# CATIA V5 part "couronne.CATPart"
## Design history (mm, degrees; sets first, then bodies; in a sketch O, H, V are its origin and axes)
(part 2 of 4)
    line L472 (-9.3364, -47.4236) -> (-9.2028, -47.1899)
    line L473 (-9.2028, -47.1899) -> (-9.0799, -46.966)
    line L474 (-9.0799, -46.966) -> (-8.9675, -46.7523)
    line L475 (-8.9675, -46.7523) -> (-8.8651, -46.5492)
    line L476 (-8.8651, -46.5492) -> (-8.804, -46.4225)
    arc A211 centre (0, 0) radius 47.25 from (-8.8041, -46.4225) to (-7.6045, -46.634) ccw
    line L477 (-7.6045, -46.634) -> (-7.6016, -46.666)
    line L478 (-7.6016, -46.666) -> (-7.5776, -46.8853)
    line L479 (-7.5776, -46.8853) -> (-7.548, -47.1179)
    line L480 (-7.548, -47.1179) -> (-7.5124, -47.3637)
    line L481 (-7.5124, -47.3637) -> (-7.4702, -47.6226)
    line L482 (-7.4702, -47.6226) -> (-7.421, -47.8944)
    line L483 (-7.421, -47.8944) -> (-7.3644, -48.1789)
    line L484 (-7.3644, -48.1789) -> (-7.2999, -48.476)
    line L485 (-7.2999, -48.476) -> (-7.2271, -48.7855)
    line L486 (-7.2271, -48.7855) -> (-7.1454, -49.1071)
    line L487 (-7.1454, -49.1071) -> (-7.0544, -49.4407)
    line L488 (-7.0544, -49.4407) -> (-7.0115, -49.5879)
    arc A212 centre (-6.5329, -49.4032) radius 0.513 from (-7.0115, -49.5879) to (-7.0052, -49.6036) ccw
    arc A213 centre (-6.5502, -49.3666) radius 0.513 from (-7.0052, -49.6036) to (-6.9552, -49.6814) ccw
    arc A214 centre (-6.5684, -49.3445) radius 0.513 from (-6.9552, -49.6814) to (-6.7664, -49.8178) ccw
    arc A215 centre (-6.5881, -49.3367) radius 0.513 from (-6.7664, -49.8178) to (-6.6686, -49.8434) ccw
    arc A216 centre (0, 0) radius 50.2875 from (-6.6686, -49.8434) to (-6.4517, -49.8719) ccw
    arc A217 centre (-6.4159, -49.3602) radius 0.513 from (-6.4517, -49.8719) to (-6.2238, -49.8358) ccw
    arc A218 centre (-6.438, -49.3697) radius 0.513 from (-6.2238, -49.8358) to (-6.0946, -49.7508) ccw
    arc A219 centre (-6.4627, -49.3935) radius 0.513 from (-6.0946, -49.7508) to (-6.0629, -49.7149) ccw
    arc A220 centre (-6.4904, -49.4314) radius 0.513 from (-6.0629, -49.7149) to (-6.0495, -49.6937) ccw
    line L489 (-6.0495, -49.6937) -> (-5.8935, -49.4314)
    line L490 (-5.8935, -49.4314) -> (-5.7254, -49.1373)
    line L491 (-5.7254, -49.1373) -> (-5.5691, -48.8524)
    line L492 (-5.5691, -48.8524) -> (-5.4243, -48.5772)
    line L493 (-5.4243, -48.5772) -> (-5.2906, -48.3119)
    line L494 (-5.2906, -48.3119) -> (-5.1676, -48.0569)
    line L495 (-5.1676, -48.0569) -> (-5.0549, -47.8124)
    line L496 (-5.0549, -47.8124) -> (-4.952, -47.5787)
    line L497 (-4.952, -47.5787) -> (-4.8587, -47.356)
    line L498 (-4.8587, -47.356) -> (-4.7744, -47.1447)
    line L499 (-4.7744, -47.1447) -> (-4.7245, -47.0132)
    arc A221 centre (0, 0) radius 47.25 from (-4.7245, -47.0132) to (-3.5112, -47.1194) ccw
    line L500 (-3.5112, -47.1194) -> (-3.5055, -47.151)
    line L501 (-3.5055, -47.151) -> (-3.4624, -47.3673)
    line L502 (-3.4624, -47.3673) -> (-3.4127, -47.5964)
    line L503 (-3.4127, -47.5964) -> (-3.3558, -47.8382)
    line L504 (-3.3558, -47.8382) -> (-3.2912, -48.0924)
    line L505 (-3.2912, -48.0924) -> (-3.2185, -48.3589)
    line L506 (-3.2185, -48.3589) -> (-3.1374, -48.6374)
    line L507 (-3.1374, -48.6374) -> (-3.0472, -48.9278)
    line L508 (-3.0472, -48.9278) -> (-2.9476, -49.2297)
    line L509 (-2.9476, -49.2297) -> (-2.8382, -49.543)
    line L510 (-2.8382, -49.543) -> (-2.7185, -49.8674)
    line L511 (-2.7185, -49.8674) -> (-2.663, -50.0103)
    arc A222 centre (-2.2023, -49.7846) radius 0.513 from (-2.663, -50.0103) to (-2.6553, -50.0254) ccw
    arc A223 centre (-2.2227, -49.7497) radius 0.513 from (-2.6553, -50.0254) to (-2.5988, -50.0986) ccw
    arc A224 centre (-2.2428, -49.7292) radius 0.513 from (-2.5988, -50.0986) to (-2.3987, -50.2179) ccw
    arc A225 centre (-2.2631, -49.7232) radius 0.513 from (-2.3987, -50.2179) to (-2.2991, -50.2349) ccw
    arc A226 centre (0, 0) radius 50.2875 from (-2.2991, -50.2349) to (-2.0805, -50.2444) ccw
    arc A227 centre (-2.0895, -49.7315) radius 0.513 from (-2.0805, -50.2444) to (-1.8566, -50.1886) ccw
    arc A228 centre (-2.1107, -49.743) radius 0.513 from (-1.8566, -50.1886) to (-1.7353, -50.0926) ccw
    arc A229 centre (-2.1332, -49.7688) radius 0.513 from (-1.7353, -50.0926) to (-1.7068, -50.0541) ccw
    arc A230 centre (-2.1575, -49.809) radius 0.513 from (-1.7068, -50.0541) to (-1.6954, -50.0318) ccw
    line L512 (-1.6954, -50.0318) -> (-1.5629, -49.757)
    line L513 (-1.5629, -49.757) -> (-1.421, -49.4493)
    line L514 (-1.421, -49.4493) -> (-1.2902, -49.1519)
    line L515 (-1.2902, -49.1519) -> (-1.1699, -48.8651)
    line L516 (-1.1699, -48.8651) -> (-1.0598, -48.5892)
    line L517 (-1.0598, -48.5892) -> (-0.9595, -48.3244)
    line L518 (-0.9595, -48.3244) -> (-0.8685, -48.071)
    line L519 (-0.8685, -48.071) -> (-0.7864, -47.8292)
    line L520 (-0.7864, -47.8292) -> (-0.7128, -47.5993)
    line L521 (-0.7128, -47.5993) -> (-0.6473, -47.3814)
    line L522 (-0.6473, -47.3814) -> (-0.6091, -47.2461)
    arc A231 centre (0, 0) radius 47.25 from (-0.6091, -47.2461) to (0.6089, -47.2461) ccw
    line L523 (0.6089, -47.2461) -> (0.6174, -47.2771)
    line L524 (0.6174, -47.2771) -> (0.6791, -47.4888)
    line L525 (0.6791, -47.4888) -> (0.7486, -47.7127)
    line L526 (0.7486, -47.7127) -> (0.8264, -47.9486)
    line L527 (0.8264, -47.9486) -> (0.9129, -48.1963)
    line L528 (0.9129, -48.1963) -> (1.0085, -48.4554)
    line L529 (1.0085, -48.4554) -> (1.1136, -48.7258)
    line L530 (1.1136, -48.7258) -> (1.2287, -49.0072)
    line L531 (1.2287, -49.0072) -> (1.3542, -49.2993)
    line L532 (1.3542, -49.2993) -> (1.4905, -49.6019)
    line L533 (1.4905, -49.6019) -> (1.638, -49.9146)
    line L534 (1.638, -49.9146) -> (1.7058, -50.0521)
    arc A232 centre (2.1451, -49.7871) radius 0.513 from (1.7058, -50.0521) to (1.7148, -50.0665) ccw
    arc A233 centre (2.1217, -49.7541) radius 0.513 from (1.7148, -50.0665) to (1.7775, -50.1344) ccw
    arc A234 centre (2.1, -49.7354) radius 0.513 from (1.7775, -50.1344) to (1.9872, -50.2359) ccw
    arc A235 centre (2.0792, -49.7312) radius 0.513 from (1.9872, -50.2359) to (2.0879, -50.2441) ccw
    arc A236 centre (0, 0) radius 50.2875 from (2.0879, -50.2441) to (2.3065, -50.2346) ccw
    arc A237 centre (2.2528, -49.7244) radius 0.513 from (2.3065, -50.2346) to (2.5247, -50.1595) ccw
    arc A238 centre (2.2327, -49.7376) radius 0.513 from (2.5247, -50.1595) to (2.6371, -50.0532) ccw
    arc A239 centre (2.2126, -49.7653) radius 0.513 from (2.6371, -50.0532) to (2.6622, -50.0124) ccw
    arc A240 centre (2.1919, -49.8075) radius 0.513 from (2.6622, -50.0124) to (2.6716, -49.9892) ccw
    line L535 (2.6716, -49.9892) -> (2.7797, -49.7039)
    line L536 (2.7797, -49.7039) -> (2.8942, -49.385)
    line L537 (2.8942, -49.385) -> (2.9986, -49.0773)
    line L538 (2.9986, -49.0773) -> (3.0934, -48.7811)
    line L539 (3.0934, -48.7811) -> (3.179, -48.4967)
    line L540 (3.179, -48.4967) -> (3.2559, -48.2241)
    line L541 (3.2559, -48.2241) -> (3.3245, -47.9638)
    line L542 (3.3245, -47.9638) -> (3.3851, -47.7157)
    line L543 (3.3851, -47.7157) -> (3.4384, -47.4803)
    line L544 (3.4384, -47.4803) -> (3.4848, -47.2575)
    line L545 (3.4848, -47.2575) -> (3.511, -47.1194)
    arc A241 centre (0, 0) radius 47.25 from (3.511, -47.1194) to (4.7243, -47.0132) ccw
    line L546 (4.7244, -47.0132) -> (4.7355, -47.0434)
    line L547 (4.7355, -47.0434) -> (4.8154, -47.2489)
    line L548 (4.8154, -47.2489) -> (4.9042, -47.4659)
    line L549 (4.9042, -47.4659) -> (5.0022, -47.6941)
    line L550 (5.0022, -47.6941) -> (5.11, -47.9333)
    line L551 (5.11, -47.9333) -> (5.2278, -48.1831)
    line L552 (5.2278, -48.1831) -> (5.3561, -48.4433)
    line L553 (5.3561, -48.4433) -> (5.4953, -48.7136)
    line L554 (5.4953, -48.7136) -> (5.6458, -48.9937)
    line L555 (5.6458, -48.9937) -> (5.808, -49.2832)
    line L556 (5.808, -49.2832) -> (5.9822, -49.5819)
    line L557 (5.9822, -49.5819) -> (6.0617, -49.713)
    arc A242 centre (6.4762, -49.4107) radius 0.513 from (6.0617, -49.713) to (6.0719, -49.7265) ccw
    arc A243 centre (6.45, -49.3798) radius 0.513 from (6.0719, -49.7265) to (6.1403, -49.7887) ccw
    arc A244 centre (6.4267, -49.3632) radius 0.513 from (6.1403, -49.7887) to (6.358, -49.8715) ccw
    arc A245 centre (6.4057, -49.3608) radius 0.513 from (6.358, -49.8715) to (6.459, -49.871) ccw
    arc A246 centre (0, 0) radius 50.2875 from (6.459, -49.871) to (6.6759, -49.8424) ccw
    arc A247 centre (6.578, -49.3388) radius 0.513 from (6.6759, -49.8424) to (6.8867, -49.7486) ccw
    arc A248 centre (6.5591, -49.3538) radius 0.513 from (6.8867, -49.7486) to (6.9895, -49.6329) ccw
    arc A249 centre (6.5415, -49.3831) radius 0.513 from (6.9895, -49.6329) to (7.0109, -49.59) ccw
    arc A250 centre (6.5245, -49.4269) radius 0.513 from (7.0109, -49.59) to (7.0183, -49.5661) ccw
    line L558 (7.0183, -49.5661) -> (7.1011, -49.2725)
    line L559 (7.1011, -49.2725) -> (7.1873, -48.9448)
    line L560 (7.1873, -48.9448) -> (7.2646, -48.6292)
    line L561 (7.2646, -48.6292) -> (7.3332, -48.3259)
    line L562 (7.3332, -48.3259) -> (7.3937, -48.0351)
    line L563 (7.3937, -48.0351) -> (7.4465, -47.7569)
    line L564 (7.4465, -47.7569) -> (7.4921, -47.4915)
    line L565 (7.4921, -47.4915) -> (7.531, -47.2391)
    line L566 (7.531, -47.2391) -> (7.5635, -46.9999)
    line L567 (7.5635, -46.9999) -> (7.5903, -46.774)
    line L568 (7.5903, -46.774) -> (7.6043, -46.6341)
    arc A251 centre (0, 0) radius 47.25 from (7.6043, -46.6341) to (8.8039, -46.4226) ccw
    line L569 (8.8039, -46.4226) -> (8.8176, -46.4516)
    line L570 (8.8176, -46.4516) -> (8.9151, -46.6494)
    line L571 (8.9151, -46.6494) -> (9.0225, -46.8579)
    line L572 (9.0225, -46.8579) -> (9.14, -47.0767)
    line L573 (9.14, -47.0767) -> (9.2682, -47.3055)
    line L574 (9.2682, -47.3055) -> (9.4073, -47.5441)
    line L575 (9.4073, -47.5441) -> (9.5578, -47.7922)
    line L576 (9.5578, -47.7922) -> (9.7201, -48.0493)
    line L577 (9.7201, -48.0493) -> (9.8944, -48.3152)
    line L578 (9.8944, -48.3152) -> (10.0812, -48.5895)
    line L579 (10.0812, -48.5895) -> (10.2807, -48.8719)
    line L580 (10.2807, -48.8719) -> (10.3714, -48.9955)
    arc A252 centre (10.7579, -48.6582) radius 0.513 from (10.3714, -48.9955) to (10.3827, -49.0081) ccw
    arc A253 centre (10.7292, -48.6298) radius 0.513 from (10.3827, -49.0081) to (10.4563, -49.0641) ccw
    arc A254 centre (10.7045, -48.6152) radius 0.513 from (10.4563, -49.0641) to (10.6804, -49.1276) ccw
    arc A255 centre (10.6834, -48.6146) radius 0.513 from (10.6804, -49.1276) to (10.781, -49.1183) ccw
    arc A256 centre (0, 0) radius 50.2875 from (10.7809, -49.1183) to (10.9946, -49.0709) ccw
    arc A257 centre (10.8532, -48.5778) radius 0.513 from (10.9946, -49.0709) to (11.1964, -48.959) ccw
    arc A258 centre (10.8356, -48.5943) radius 0.513 from (11.1964, -48.959) to (11.2887, -48.8349) ccw
    arc A259 centre (10.8206, -48.6251) radius 0.513 from (11.2887, -48.8349) to (11.3063, -48.7903) ccw
    arc A260 centre (10.8075, -48.6702) radius 0.513 from (11.3063, -48.7903) to (11.3115, -48.7658) ccw
    line L581 (11.3115, -48.7658) -> (11.3684, -48.4661)
    line L582 (11.3684, -48.4661) -> (11.4258, -48.1321)
    line L583 (11.4258, -48.1321) -> (11.4752, -47.811)
    line L584 (11.4752, -47.811) -> (11.5172, -47.5029)
    line L585 (11.5172, -47.5029) -> (11.5521, -47.2079)
    line L586 (11.5521, -47.2079) -> (11.5805, -46.9261)
    line L587 (11.5805, -46.9261) -> (11.6028, -46.6578)
    line L588 (11.6028, -46.6578) -> (11.6195, -46.403)
    line L589 (11.6195, -46.403) -> (11.631, -46.1619)
    line L590 (11.631, -46.1619) -> (11.638, -45.9345)
    line L591 (11.638, -45.9345) -> (11.6398, -45.7938)
    arc A261 centre (0, 0) radius 47.25 from (11.6399, -45.7938) to (12.8163, -45.4786) ccw
    line L592 (12.8163, -45.4786) -> (12.8325, -45.5064)
    line L593 (12.8325, -45.5064) -> (12.9469, -45.6949)
    line L594 (12.9469, -45.6949) -> (13.0721, -45.8932)
    line L595 (13.0721, -45.8932) -> (13.2083, -46.1009)
    line L596 (13.2083, -46.1009) -> (13.3559, -46.3177)
    line L597 (13.3559, -46.3177) -> (13.5153, -46.5433)
    line L598 (13.5153, -46.5433) -> (13.6868, -46.7773)
    line L599 (13.6868, -46.7773) -> (13.8709, -47.0193)
    line L600 (13.8709, -47.0193) -> (14.0677, -47.269)
    line L601 (14.0677, -47.269) -> (14.2777, -47.526)
    line L602 (14.2777, -47.526) -> (14.5011, -47.7899)
    line L603 (14.5011, -47.7899) -> (14.6021, -47.9051)
    arc A262 centre (14.9578, -47.5354) radius 0.513 from (14.6021, -47.9051) to (14.6146, -47.9167) ccw
    arc A263 centre (14.9268, -47.5096) radius 0.513 from (14.6146, -47.9167) to (14.6927, -47.9661) ccw
    arc A264 centre (14.9009, -47.4972) radius 0.513 from (14.6927, -47.9661) to (14.9215, -48.0098) ccw
    arc A265 centre (14.8798, -47.4985) radius 0.513 from (14.9215, -48.0098) to (15.0209, -47.9917) ccw
    arc A266 centre (0, 0) radius 50.2875 from (15.0209, -47.9917) to (15.2296, -47.9259) ccw
    arc A267 centre (15.0457, -47.447) radius 0.513 from (15.2296, -47.9259) to (15.4209, -47.7969) ccw
    arc A268 centre (15.0297, -47.465) radius 0.513 from (15.4209, -47.7969) to (15.502, -47.6652) ccw
    arc A269 centre (15.0174, -47.497) radius 0.513 from (15.502, -47.6652) to (15.5156, -47.6192) ccw
    arc A270 centre (15.0083, -47.543) radius 0.513 from (15.5156, -47.6192) to (15.5187, -47.5944) ccw
    line L604 (15.5187, -47.5944) -> (15.5493, -47.2908)
    line L605 (15.5493, -47.2908) -> (15.5773, -46.9532)
    line L606 (15.5773, -46.9532) -> (15.5986, -46.629)
    line L607 (15.5986, -46.629) -> (15.6135, -46.3183)
    line L608 (15.6135, -46.3183) -> (15.6226, -46.0214)
    line L609 (15.6226, -46.0214) -> (15.6263, -45.7383)
    line L610 (15.6263, -45.7383) -> (15.6251, -45.469)
    line L611 (15.6251, -45.469) -> (15.6195, -45.2137)
    line L612 (15.6195, -45.2137) -> (15.6101, -44.9725)
    line L613 (15.6101, -44.9725) -> (15.5972, -44.7453)
    line L614 (15.5972, -44.7453) -> (15.5867, -44.6051)
    arc A271 centre (0, 0) radius 47.25 from (15.5867, -44.6051) to (16.7313, -44.1885) ccw
    line L615 (16.7313, -44.1885) -> (16.7498, -44.2148)
    line L616 (16.7498, -44.2148) -> (16.8803, -44.3926)
    line L617 (16.8803, -44.3926) -> (17.0222, -44.5793)
    line L618 (17.0222, -44.5793) -> (17.176, -44.7743)
    line L619 (17.176, -44.7743) -> (17.3419, -44.9775)
    line L620 (17.3419, -44.9775) -> (17.5204, -45.1883)
    line L621 (17.5204, -45.1883) -> (17.7117, -45.4064)
    line L622 (17.7117, -45.4064) -> (17.9161, -45.6314)
    line L623 (17.9161, -45.6314) -> (18.1339, -45.863)
    line L624 (18.1339, -45.863) -> (18.3655, -46.1007)
    line L625 (18.3655, -46.1007) -> (18.6111, -46.3442)
    line L626 (18.6111, -46.3442) -> (18.7218, -46.4502)
    arc A272 centre (19.0439, -46.0509) radius 0.513 from (18.7218, -46.4502) to (18.7352, -46.4606) ccw
    arc A273 centre (19.0107, -46.0279) radius 0.513 from (18.7352, -46.4606) to (18.8173, -46.503) ccw
    arc A274 centre (18.9838, -46.0178) radius 0.513 from (18.8173, -46.503) to (19.049, -46.5266) ccw
    arc A275 centre (18.9629, -46.0209) radius 0.513 from (19.049, -46.5266) to (19.1465, -46.4999) ccw
    arc A276 centre (0, 0) radius 50.2875 from (19.1465, -46.5) to (19.3486, -46.4162) ccw
    arc A277 centre (19.1237, -45.9551) radius 0.513 from (19.3486, -46.4162) to (19.5279, -46.271) ccw
    arc A278 centre (19.1093, -45.9744) radius 0.513 from (19.5279, -46.271) to (19.5973, -46.1327) ccw
    arc A279 centre (19.0999, -46.0074) radius 0.513 from (19.5973, -46.1327) to (19.6068, -46.0858) ccw
    arc A280 centre (19.0948, -46.054) radius 0.513 from (19.6068, -46.0858) to (19.6078, -46.0608) ccw
    line L627 (19.6078, -46.0608) -> (19.6118, -45.7556)
    line L628 (19.6118, -45.7556) -> (19.6103, -45.4168)
    line L629 (19.6103, -45.4168) -> (19.6032, -45.092)
    line L630 (19.6032, -45.092) -> (19.591, -44.7813)
    line L631 (19.591, -44.7813) -> (19.5742, -44.4847)
    line L632 (19.5742, -44.4847) -> (19.5532, -44.2023)
    line L633 (19.5532, -44.2023) -> (19.5285, -43.9342)
    line L634 (19.5285, -43.9342) -> (19.5007, -43.6803)
    line L635 (19.5007, -43.6803) -> (19.4703, -43.4409)
    line L636 (19.4703, -43.4409) -> (19.4376, -43.2157)
    line L637 (19.4376, -43.2157) -> (19.415, -43.0769)
    arc A281 centre (0, 0) radius 47.25 from (19.415, -43.0769) to (20.5189, -42.5622) ccw
    line L638 (20.5189, -42.5622) -> (20.5397, -42.5867)
    line L639 (20.5397, -42.5867) -> (20.6851, -42.7525)
    line L640 (20.6851, -42.7525) -> (20.8427, -42.9261)
    line L641 (20.8427, -42.9261) -> (21.0129, -43.107)
    line L642 (21.0129, -43.107) -> (21.196, -43.2949)
    line L643 (21.196, -43.2949) -> (21.3921, -43.4893)
    line L644 (21.3921, -43.4893) -> (21.6017, -43.6899)
    line L645 (21.6017, -43.6899) -> (21.8249, -43.8963)
    line L646 (21.8249, -43.8963) -> (22.0622, -44.108)
    line L647 (22.0622, -44.108) -> (22.3136, -44.3246)
    line L648 (22.3136, -44.3246) -> (22.5794, -44.5457)
    line L649 (22.5794, -44.5457) -> (22.6989, -44.6417)
    arc A282 centre (22.985, -44.2159) radius 0.513 from (22.6989, -44.6417) to (22.7132, -44.6509) ccw
    arc A283 centre (22.9499, -44.1958) radius 0.513 from (22.7132, -44.6509) to (22.7987, -44.686) ccw
    arc A284 centre (22.9223, -44.1881) radius 0.513 from (22.7987, -44.686) to (23.0316, -44.6894) ccw
    arc A285 centre (22.9017, -44.1931) radius 0.513 from (23.0316, -44.6894) to (23.1264, -44.6543) ccw
    arc A286 centre (0, 0) radius 50.2875 from (23.1264, -44.6543) to (23.3204, -44.5532) ccw
    arc A287 centre (23.0562, -44.1135) radius 0.513 from (23.3204, -44.5532) to (23.4864, -44.3929) ccw
    arc A288 centre (23.0436, -44.134) radius 0.513 from (23.4864, -44.3929) to (23.5435, -44.2491) ccw
    arc A289 centre (23.037, -44.1676) radius 0.513 from (23.5435, -44.2491) to (23.5489, -44.2015) ccw
    arc A290 centre (23.036, -44.2146) radius 0.513 from (23.5489, -44.2015) to (23.5476, -44.1766) ccw
    line L650 (23.5476, -44.1766) -> (23.525, -43.8723)
    line L651 (23.525, -43.8723) -> (23.494, -43.5349)
    line L652 (23.494, -43.5349) -> (23.4586, -43.2119)
    line L653 (23.4586, -43.2119) -> (23.4194, -42.9034)
    line L654 (23.4194, -42.9034) -> (23.3768, -42.6094)
    line L655 (23.3768, -42.6094) -> (23.3313, -42.3299)
    line L656 (23.3313, -42.3299) -> (23.2833, -42.065)
    line L657 (23.2833, -42.065) -> (23.2335, -41.8145)
    line L658 (23.2335, -41.8145) -> (23.1823, -41.5786)
    line L659 (23.1823, -41.5786) -> (23.1302, -41.3571)
    line L660 (23.1302, -41.3571) -> (23.0955, -41.2209)
    arc A291 centre (0, 0) radius 47.25 from (23.0955, -41.2209) to (24.1504, -40.6118) ccw
    line L661 (24.1504, -40.6118) -> (24.1732, -40.6345)
    line L662 (24.1732, -40.6345) -> (24.3325, -40.787)
    line L663 (24.3325, -40.787) -> (24.5047, -40.9461)
    line L664 (24.5047, -40.9461) -> (24.69, -41.1115)
    line L665 (24.69, -41.1115) -> (24.8887, -41.2828)
    line L666 (24.8887, -41.2828) -> (25.1011, -41.4594)
    line L667 (25.1011, -41.4594) -> (25.3273, -41.641)
    line L668 (25.3273, -41.641) -> (25.5677, -41.8271)
    line L669 (25.5677, -41.8271) -> (25.8225, -42.0173)
    line L670 (25.8225, -42.0173) -> (26.0918, -42.2112)
    line L671 (26.0918, -42.2112) -> (26.3759, -42.4083)
    line L672 (26.3759, -42.4083) -> (26.5033, -42.4935)
    arc A292 centre (26.7512, -42.0443) radius 0.513 from (26.5033, -42.4935) to (26.5183, -42.5014) ccw
    arc A293 centre (26.7145, -42.0274) radius 0.513 from (26.5183, -42.5014) to (26.6066, -42.5289) ccw
    arc A294 centre (26.6863, -42.0222) radius 0.513 from (26.6066, -42.5289) to (26.8389, -42.512) ccw
    arc A295 centre (26.6663, -42.0289) radius 0.513 from (26.8389, -42.512) to (26.9302, -42.4688) ccw
    arc A296 centre (0, 0) radius 50.2875 from (26.9302, -42.4688) to (27.1147, -42.3512) ccw
    arc A297 centre (26.8132, -41.9362) radius 0.513 from (27.1148, -42.3512) to (27.2661, -42.177) ccw
    arc A298 centre (26.8024, -41.9577) radius 0.513 from (27.2661, -42.177) to (27.3105, -42.0288) ccw
    arc A299 centre (26.7988, -41.9918) radius 0.513 from (27.3105, -42.0288) to (27.3117, -41.9809) ccw
    arc A300 centre (26.8019, -42.0386) radius 0.513 from (27.3117, -41.9809) to (27.3083, -41.9561) ccw
    line L673 (27.3083, -41.9561) -> (27.2592, -41.655)
    line L674 (27.2592, -41.655) -> (27.1989, -41.3216)
    line L675 (27.1989, -41.3216) -> (27.1355, -41.0029)
    line L676 (27.1355, -41.0029) -> (27.0696, -40.699)
    line L677 (27.0696, -40.699) -> (27.0015, -40.4098)
    line L678 (27.0015, -40.4098) -> (26.9318, -40.1354)
    line L679 (26.9318, -40.1354) -> (26.8609, -39.8756)
    line L680 (26.8609, -39.8756) -> (26.7895, -39.6305)
    line L681 (26.7895, -39.6305) -> (26.7179, -39.3999)
    line L682 (26.7179, -39.3999) -> (26.6466, -39.1838)
    line L683 (26.6466, -39.1838) -> (26.6003, -39.0511)
    arc A301 centre (0, 0) radius 47.25 from (26.6003, -39.0511) to (27.598, -38.3525) ccw
    line L684 (27.598, -38.3525) -> (27.6227, -38.373)
    line L685 (27.6227, -38.373) -> (27.7947, -38.5111)
    line L686 (27.7947, -38.5111) -> (27.9801, -38.6546)
    line L687 (27.9801, -38.6546) -> (28.1791, -38.8032)
    line L688 (28.1791, -38.8032) -> (28.392, -38.9565)
    line L689 (28.392, -38.9565) -> (28.619, -39.1139)
    line L690 (28.619, -39.1139) -> (28.8602, -39.2751)
    line L691 (28.8602, -39.2751) -> (29.1159, -39.4396)
    line L692 (29.1159, -39.4396) -> (29.3863, -39.6069)
    line L693 (29.3863, -39.6069) -> (29.6715, -39.7765)
    line L694 (29.6715, -39.7765) -> (29.9716, -39.9481)
    line L695 (29.9716, -39.9481) -> (30.106, -40.0218)
    arc A302 centre (30.3138, -39.5528) radius 0.513 from (30.106, -40.0218) to (30.1217, -40.0285) ccw
    arc A303 centre (30.2758, -39.5392) radius 0.513 from (30.1217, -40.0285) to (30.212, -40.0482) ccw
    arc A304 centre (30.2473, -39.5364) radius 0.513 from (30.212, -40.0482) to (30.4419, -40.011) ccw
    arc A305 centre (30.2278, -39.5448) radius 0.513 from (30.4419, -40.011) to (30.5291, -39.96) ccw
    arc A306 centre (0, 0) radius 50.2875 from (30.5292, -39.96) to (30.7027, -39.8268) ccw
    arc A307 centre (30.3662, -39.4397) radius 0.513 from (30.7027, -39.8268) to (30.8384, -39.6401) ccw
    arc A308 centre (30.3573, -39.462) radius 0.513 from (30.8384, -39.6401) to (30.8696, -39.4886) ccw
    arc A309 centre (30.3566, -39.4963) radius 0.513 from (30.8696, -39.4886) to (30.8666, -39.4408) ccw
    arc A310 centre (30.3638, -39.5427) radius 0.513 from (30.8666, -39.4408) to (30.8611, -39.4164) ccw
    line L696 (30.8611, -39.4164) -> (30.786, -39.1207)
    line L697 (30.786, -39.1207) -> (30.6968, -38.7938)
    line L698 (30.6968, -38.7938) -> (30.6059, -38.4819)
    line L699 (30.6059, -38.4819) -> (30.5137, -38.1849)
    line L700 (30.5137, -38.1849) -> (30.4207, -37.9027)
    line L701 (30.4207, -37.9027) -> (30.3273, -37.6354)
    line L702 (30.3273, -37.6354) -> (30.2341, -37.3828)
    line L703 (30.2341, -37.3828) -> (30.1416, -37.1448)
    line L704 (30.1416, -37.1448) -> (30.0502, -36.9214)
    line L705 (30.0502, -36.9214) -> (29.9603, -36.7123)
    line L706 (29.9603, -36.7123) -> (29.9026, -36.5841)
    arc A311 centre (0, 0) radius 47.25 from (29.9026, -36.5841) to (30.8357, -35.8012) ccw
    line L707 (30.8356, -35.8012) -> (30.862, -35.8195)
    line L708 (30.862, -35.8195) -> (31.0454, -35.942)
    line L709 (31.0454, -35.942) -> (31.2426, -36.0689)
    line L710 (31.2426, -36.0689) -> (31.4538, -36.1996)
    line L711 (31.4538, -36.1996) -> (31.6793, -36.3337)
    line L712 (31.6793, -36.3337) -> (31.9191, -36.4708)
    line L713 (31.9191, -36.4708) -> (32.1734, -36.6103)
    line L714 (32.1734, -36.6103) -> (32.4425, -36.7519)
    line L715 (32.4425, -36.7519) -> (32.7264, -36.895)
    line L716 (32.7264, -36.895) -> (33.0253, -37.0391)
    line L717 (33.0253, -37.0391) -> (33.3393, -37.1839)
    line L718 (33.3393, -37.1839) -> (33.4796, -37.2456)
    arc A312 centre (33.6457, -36.7603) radius 0.513 from (33.4796, -37.2456) to (33.4958, -37.2509) ccw
    arc A313 centre (33.6067, -36.75) radius 0.513 from (33.4958, -37.2509) to (33.5874, -37.2626) ccw
    arc A314 centre (33.578, -36.7497) radius 0.513 from (33.5874, -37.2626) to (33.8133, -37.2056) ccw
    arc A315 centre (33.5594, -36.7598) radius 0.513 from (33.8133, -37.2056) to (33.8957, -37.1472) ccw
    arc A316 centre (0, 0) radius 50.2875 from (33.8957, -37.1472) to (34.057, -36.9994) ccw
    arc A317 centre (33.688, -36.643) radius 0.513 from (34.057, -36.9993) to (34.1759, -36.8016) ccw
    arc A318 centre (33.6811, -36.6661) radius 0.513 from (34.1759, -36.8016) to (34.1938, -36.6479) ccw
    arc A319 centre (33.6835, -36.7002) radius 0.513 from (34.1938, -36.6479) to (34.1867, -36.6005) ccw
    arc A320 centre (33.6947, -36.7458) radius 0.513 from (34.1867, -36.6005) to (34.179, -36.5767) ccw
    line L719 (34.179, -36.5767) -> (34.0784, -36.2886)
    line L720 (34.0784, -36.2886) -> (33.9611, -35.9708)
    line L721 (33.9611, -35.9708) -> (33.8434, -35.6679)
    line L722 (33.8434, -35.6679) -> (33.7256, -35.3801)
    line L723 (33.7256, -35.3801) -> (33.6083, -35.1072)
    line L724 (33.6083, -35.1072) -> (33.492, -34.849)
    line L725 (33.492, -34.849) -> (33.3772, -34.6055)
    line L726 (33.3772, -34.6055) -> (33.2643, -34.3765)
    line L727 (33.2643, -34.3765) -> (33.1537, -34.1618)
    line L728 (33.1537, -34.1618) -> (33.046, -33.9614)
    line L729 (33.046, -33.9614) -> (32.9773, -33.8387)
    arc A321 centre (0, 0) radius 47.25 from (32.9773, -33.8387) to (33.8386, -32.9775) ccw
    line L730 (33.8386, -32.9775) -> (33.8665, -32.9934)
    line L731 (33.8665, -32.9934) -> (34.0598, -33.0995)
    line L732 (34.0598, -33.0995) -> (34.2674, -33.2087)
    line L733 (34.2674, -33.2087) -> (34.4892, -33.3205)
    line L734 (34.4892, -33.3205) -> (34.7254, -33.4344)
    line L735 (34.7254, -33.4344) -> (34.9762, -33.55)
    line L736 (34.9762, -33.55) -> (35.2418, -33.6669)
    line L737 (35.2418, -33.6669) -> (35.5222, -33.7845)
    line L738 (35.5222, -33.7845) -> (35.8175, -33.9023)
    line L739 (35.8175, -33.9023) -> (36.1278, -34.0199)
    line L740 (36.1278, -34.0199) -> (36.4532, -34.1367)
    line L741 (36.4532, -34.1367) -> (36.5984, -34.186)
    arc A322 centre (36.7216, -33.688) radius 0.513 from (36.5984, -34.186) to (36.6149, -34.1898) ccw
    arc A323 centre (36.6817, -33.6811) radius 0.513 from (36.6149, -34.1898) to (36.7073, -34.1935) ccw
    arc A324 centre (36.6532, -33.6834) radius 0.513 from (36.7073, -34.1935) to (36.9273, -34.117) ccw
    arc A325 centre (36.6355, -33.695) radius 0.513 from (36.9273, -34.117) to (37.0043, -34.0516) ccw
    arc A326 centre (0, 0) radius 50.2875 from (37.0043, -34.0516) to (37.1521, -33.8903) ccw
    arc A327 centre (36.7535, -33.5675) radius 0.513 from (37.1521, -33.8903) to (37.2533, -33.6829) ccw
    arc A328 centre (36.7486, -33.591) radius 0.513 from (37.2533, -33.6829) to (37.2577, -33.5283) ccw
    arc A329 centre (36.7539, -33.6249) radius 0.513 from (37.2577, -33.5283) to (37.2465, -33.4817) ccw
    arc A330 centre (36.7691, -33.6693) radius 0.513 from (37.2465, -33.4817) to (37.2368, -33.4586) ccw
    line L742 (37.2368, -33.4586) -> (37.1115, -33.1804)
    line L743 (37.1115, -33.1804) -> (36.967, -32.874)
    line L744 (36.967, -32.874) -> (36.8233, -32.5826)
    line L745 (36.8233, -32.5826) -> (36.6809, -32.3061)
    line L746 (36.6809, -32.3061) -> (36.5402, -32.0444)
    line L747 (36.5402, -32.0444) -> (36.4019, -31.7974)
    line L748 (36.4019, -31.7974) -> (36.2662, -31.5648)
    line L749 (36.2662, -31.5648) -> (36.1338, -31.3465)
    line L750 (36.1338, -31.3465) -> (36.005, -31.1423)
    line L751 (36.005, -31.1423) -> (35.8802, -30.952)
    line L752 (35.8802, -30.952) -> (35.8011, -30.8358)
    arc A331 centre (0, 0) radius 47.25 from (35.8011, -30.8358) to (36.584, -29.9027) ccw
    line L753 (36.584, -29.9027) -> (36.6132, -29.9162)
    line L754 (36.6132, -29.9162) -> (36.815, -30.005)
    line L755 (36.815, -30.005) -> (37.0313, -30.0957)
    line L756 (37.0313, -30.0957) -> (37.262, -30.1877)
    line L757 (37.262, -30.1877) -> (37.5073, -30.2807)
    line L758 (37.5073, -30.2807) -> (37.7672, -30.374)
    line L759 (37.7672, -30.374) -> (38.0419, -30.4673)
    line L760 (38.0419, -30.4673) -> (38.3315, -30.5599)
    line L761 (38.3315, -30.5599) -> (38.636, -30.6516)
    line L762 (38.636, -30.6516) -> (38.9553, -30.7417)
    line L763 (38.9553, -30.7417) -> (39.2897, -30.8297)
    line L764 (39.2897, -30.8297) -> (39.4386, -30.8661)
    arc A332 centre (39.518, -30.3593) radius 0.513 from (39.4386, -30.8661) to (39.4554, -30.8685) ccw
    arc A333 centre (39.4777, -30.3559) radius 0.513 from (39.4554, -30.8685) to (39.5478, -30.8641) ccw
    arc A334 centre (39.4494, -30.3607) radius 0.513 from (39.5478, -30.8641) to (39.7603, -30.7687) ccw
    arc A335 centre (39.4328, -30.3738) radius 0.513 from (39.7603, -30.7687) to (39.8313, -30.6969) ccw
    arc A336 centre (0, 0) radius 50.2875 from (39.8313, -30.6969) to (39.9645, -30.5233) ccw
    arc A337 centre (39.5392, -30.2364) radius 0.513 from (39.9645, -30.5233) to (40.0472, -30.3079) ccw
    arc A338 centre (39.5364, -30.2604) radius 0.513 from (40.0472, -30.3079) to (40.0381, -30.1534) ccw
    arc A339 centre (39.5447, -30.2936) radius 0.513 from (40.0381, -30.1534) to (40.0229, -30.108) ccw
    arc A340 centre (39.5636, -30.3366) radius 0.513 from (40.0229, -30.108) to (40.0112, -30.0859) ccw
    line L765 (40.0112, -30.0859) -> (39.8621, -29.8197)
    line L766 (39.8621, -29.8197) -> (39.6914, -29.527)
    line L767 (39.6914, -29.527) -> (39.5229, -29.2492)
    line L768 (39.5229, -29.2492) -> (39.3569, -28.9862)
    line L769 (39.3569, -28.9862) -> (39.1941, -28.7378)
    line L770 (39.1941, -28.7378) -> (39.0347, -28.5037)
    line L771 (39.0347, -28.5037) -> (38.8793, -28.2838)
    line L772 (38.8793, -28.2838) -> (38.7283, -28.0779)
    line L773 (38.7283, -28.0779) -> (38.5822, -27.8857)
    line L774 (38.5822, -27.8857) -> (38.4413, -27.7071)
    line L775 (38.4413, -27.7071) -> (38.3524, -27.5982)
    arc A341 centre (0, 0) radius 47.25 from (38.3523, -27.5982) to (39.051, -26.6005) ccw
    line L776 (39.051, -26.6004) -> (39.0812, -26.6113)
    line L777 (39.0812, -26.6113) -> (39.2901, -26.6822)
    line L778 (39.2901, -26.6822) -> (39.5134, -26.7537)
    line L779 (39.5134, -26.7537) -> (39.7512, -26.8253)
    line L780 (39.7512, -26.8253) -> (40.0037, -26.8965)
    line L781 (40.0037, -26.8965) -> (40.2708, -26.9668)
    line L782 (40.2708, -26.9668) -> (40.5526, -27.0357)
    line L783 (40.5526, -27.0357) -> (40.8491, -27.1028)
    line L784 (40.8491, -27.1028) -> (41.1604, -27.1676)
    line L785 (41.1604, -27.1676) -> (41.4864, -27.2295)
    line L786 (41.4864, -27.2295) -> (41.8272, -27.288)
    line L787 (41.8272, -27.288) -> (41.9787, -27.3114)
    arc A342 centre (42.0136, -26.7995) radius 0.513 from (41.9787, -27.3114) to (41.9957, -27.3122) ccw
    arc A343 centre (41.9731, -26.7997) radius 0.513 from (41.9957, -27.3122) to (42.0873, -27.2999) ccw
    arc A344 centre (41.9454, -26.8069) radius 0.513 from (42.0873, -27.2999) to (42.2906, -27.1863) ccw
    arc A345 centre (41.93, -26.8215) radius 0.513 from (42.2906, -27.1863) to (42.3551, -27.1086) ccw
    arc A346 centre (0, 0) radius 50.2875 from (42.3552, -27.1085) to (42.4727, -26.924) ccw
    arc A347 centre (42.024, -26.6753) radius 0.513 from (42.4727, -26.924) to (42.5363, -26.7022) ccw
    arc A348 centre (42.0233, -26.6994) radius 0.513 from (42.5363, -26.7022) to (42.5138, -26.5491) ccw
    arc A349 centre (42.0344, -26.7318) radius 0.513 from (42.5138, -26.5491) to (42.4947, -26.5052) ccw
    arc A350 centre (42.0571, -26.7729) radius 0.513 from (42.4947, -26.5052) to (42.4811, -26.4842) ccw
    line L788 (42.4811, -26.4842) -> (42.3094, -26.232)
    line L789 (42.3094, -26.232) -> (42.1138, -25.9553)
    line L790 (42.1138, -25.9553) -> (41.9217, -25.6933)
    line L791 (41.9217, -25.6933) -> (41.7335, -25.4457)
    line L792 (41.7335, -25.4457) -> (41.5496, -25.2124)
    line L793 (41.5496, -25.2124) -> (41.3704, -24.9932)
    line L794 (41.3704, -24.9932) -> (41.1964, -24.7877)
    line L795 (41.1964, -24.7877) -> (41.0281, -24.5957)
    line L796 (41.0281, -24.5957) -> (40.8658, -24.417)
    line L797 (40.8658, -24.417) -> (40.7099, -24.2513)
    line L798 (40.7099, -24.2513) -> (40.6118, -24.1505)
    arc A351 centre (0, 0) radius 47.25 from (40.6118, -24.1505) to (41.2208, -23.0957) ccw
    line L799 (41.2208, -23.0957) -> (41.2518, -23.1039)
    line L800 (41.2518, -23.1039) -> (41.4661, -23.1563)
    line L801 (41.4661, -23.1563) -> (41.6948, -23.2081)
    line L802 (41.6948, -23.2081) -> (41.9379, -23.2586)
    line L803 (41.9379, -23.2586) -> (42.1956, -23.3076)
    line L804 (42.1956, -23.3076) -> (42.4678, -23.3543)
    line L805 (42.4678, -23.3543) -> (42.7546, -23.3985)
    line L806 (42.7546, -23.3985) -> (43.0558, -23.4395)
    line L807 (43.0558, -23.4395) -> (43.3716, -23.4768)
    line L808 (43.3716, -23.4768) -> (43.7018, -23.5101)
    line L809 (43.7018, -23.5101) -> (44.0463, -23.5387)
    line L810 (44.0463, -23.5387) -> (44.1993, -23.5487)
    arc A352 centre (44.1894, -23.0358) radius 0.513 from (44.1993, -23.5487) to (44.2163, -23.5481) ccw
    arc A353 centre (44.1492, -23.0395) radius 0.513 from (44.2163, -23.5481) to (44.3064, -23.5278) ccw
    arc A354 centre (44.1221, -23.0491) radius 0.513 from (44.3064, -23.5278) to (44.4992, -23.397) ccw
    arc A355 centre (44.1081, -23.065) radius 0.513 from (44.4992, -23.397) to (44.5566, -23.3139) ccw
    arc A356 centre (0, 0) radius 50.2875 from (44.5566, -23.3139) to (44.6577, -23.1198) ccw
    arc A357 centre (44.189, -22.9112) radius 0.513 from (44.6577, -23.1198) to (44.7017, -22.8933) ccw
    arc A358 centre (44.1904, -22.9352) radius 0.513 from (44.7017, -22.8933) to (44.666, -22.7428) ccw
    arc A359 centre (44.2043, -22.9665) radius 0.513 from (44.666, -22.7428) to (44.6431, -22.7007) ccw
    arc A360 centre (44.2305, -23.0055) radius 0.513 from (44.6431, -22.7007) to (44.6277, -22.6809) ccw
    line L811 (44.6277, -22.6809) -> (44.4347, -22.4447)
    line L812 (44.4347, -22.4447) -> (44.2157, -22.1861)
    line L813 (44.2157, -22.1861) -> (44.0015, -21.9418)
    line L814 (44.0015, -21.9418) -> (43.7924, -21.7116)
    line L815 (43.7924, -21.7116) -> (43.5889, -21.4952)
    line L816 (43.5889, -21.4952) -> (43.3913, -21.2924)
    line L817 (43.3913, -21.2924) -> (43.2001, -21.1028)
    line L818 (43.2001, -21.1028) -> (43.0156, -20.9263)
    line L819 (43.0156, -20.9263) -> (42.8383, -20.7624)
    line L820 (42.8383, -20.7624) -> (42.6686, -20.6109)
    line L821 (42.6686, -20.6109) -> (42.5621, -20.5191)
    arc A361 centre (0, 0) radius 47.25 from (42.5621, -20.5191) to (43.0768, -19.4152) ccw
    line L822 (43.0768, -19.4152) -> (43.1085, -19.4206)
    line L823 (43.1085, -19.4206) -> (43.3265, -19.4542)
    line L824 (43.3265, -19.4542) -> (43.5588, -19.4858)
    line L825 (43.5588, -19.4858) -> (43.8055, -19.515)
    line L826 (43.8055, -19.515) -> (44.0664, -19.5413)
    line L827 (44.0664, -19.5413) -> (44.3417, -19.5642)
    line L828 (44.3417, -19.5642) -> (44.6312, -19.5831)
    arc A362 centre (0, 0) radius 63 from (-62.9973, -0.5786) to (62.9973, 0.5786) ccw
    point P2 (44.6312, -19.5831)
    point P3 (44.9349, -19.5977)
    point P4 (44.9349, -19.5977)
    point P5 (45.2527, -19.6074)
    point P6 (45.2527, -19.6074)
    point P7 (45.5845, -19.6118)
    point P8 (45.5845, -19.6118)
    point P9 (45.9303, -19.6103)
    point P10 (45.9303, -19.6103)
    point P11 (46.0835, -19.6069)
    point P12 (46.0835, -19.6069)
    point P13 (46.1004, -19.6048)
    point P14 (46.1004, -19.6048)
    point P15 (46.1884, -19.5768)
    point P16 (46.1884, -19.5768)
    point P17 (46.369, -19.4296)
    point P18 (46.369, -19.4296)
    point P23 (46.5269, -18.9102)
    point P24 (46.5269, -18.9102)
    point P25 (46.4782, -18.7634)
    point P26 (46.4782, -18.7634)
    point P27 (46.4517, -18.7234)
    point P28 (46.4517, -18.7234)
    point P29 (46.4347, -18.7051)
    point P30 (46.4347, -18.7051)
    point P31 (46.2217, -18.4865)
    point P32 (46.2217, -18.4865)
    point P33 (45.9811, -18.248)
    point P34 (45.9811, -18.248)
    point P35 (45.7464, -18.0233)
    point P36 (45.7464, -18.0233)
    point P37 (45.5181, -17.8122)
    point P38 (45.5181, -17.8122)
    point P39 (45.2964, -17.6144)
    point P40 (45.2964, -17.6144)
    point P41 (45.0819, -17.4296)
    point P42 (45.0819, -17.4296)
    point P43 (44.8749, -17.2574)
    point P44 (44.8749, -17.2574)
    point P45 (44.6758, -17.0976)
    point P46 (44.6758, -17.0976)
    point P47 (44.4849, -16.9498)
    point P48 (44.4849, -16.9498)
    point P49 (44.3026, -16.8136)
    point P50 (44.3026, -16.8136)
    point P55 (44.6371, -15.5896)
    point P56 (44.6371, -15.5896)
    point P57 (44.8572, -15.604)
    point P58 (44.8572, -15.604)
    point P59 (45.0914, -15.6153)
    point P60 (45.0914, -15.6153)
    point P61 (45.3396, -15.6228)
    point P62 (45.3396, -15.6228)
    point P63 (45.6019, -15.6263)
    point P64 (45.6019, -15.6263)
    point P65 (45.8781, -15.6251)
    point P66 (45.8781, -15.6251)
    point P67 (46.1681, -15.6187)
    point P68 (46.1681, -15.6187)
    point P69 (46.4719, -15.6068)
    point P70 (46.4719, -15.6068)
    point P71 (46.7894, -15.5888)
    point P72 (46.7894, -15.5888)
    point P73 (47.1203, -15.5642)
    point P74 (47.1203, -15.5642)
    point P75 (47.4646, -15.5326)
    point P76 (47.4646, -15.5326)
    point P77 (47.617, -15.5159)
    point P78 (47.617, -15.5159)
    point P79 (47.6336, -15.5123)
    point P80 (47.6336, -15.5123)
    point P81 (47.7189, -15.4767)
    point P82 (47.7189, -15.4767)
    point P83 (47.886, -15.3143)
    point P84 (47.886, -15.3143)
    point P89 (47.998, -14.7831)
    point P90 (47.998, -14.7831)
    point P91 (47.9366, -14.6411)
    point P92 (47.9366, -14.6411)
    point P93 (47.9068, -14.6036)
    point P94 (47.9068, -14.6036)
    point P95 (47.8882, -14.5869)
    point P96 (47.8882, -14.5869)
    point P97 (47.6571, -14.3877)
    point P98 (47.6571, -14.3877)
    point P99 (47.3966, -14.171)
    point P100 (47.3966, -14.171)
    point P101 (47.1432, -13.9677)
    point P102 (47.1432, -13.9677)
    point P103 (46.8973, -13.7773)
    point P104 (46.8973, -13.7773)
    point P105 (46.6593, -13.5995)
    point P106 (46.6593, -13.5995)
    point P107 (46.4295, -13.4341)
    point P108 (46.4295, -13.4341)
    point P109 (46.2082, -13.2806)
    point P110 (46.2082, -13.2806)
    point P111 (45.9959, -13.1388)
    point P112 (45.9959, -13.1388)
    point P113 (45.7929, -13.0081)
    point P114 (45.7929, -13.0081)
    point P115 (45.5994, -12.8884)
    point P116 (45.5994, -12.8884)
    point P121 (45.8259, -11.6399)
    point P122 (45.8259, -11.6399)
    point P123 (46.0464, -11.6351)
    point P124 (46.0464, -11.6351)
    point P125 (46.2807, -11.6259)
    point P126 (46.2807, -11.6259)
    point P127 (46.5287, -11.6118)
    point P128 (46.5287, -11.6118)
    point P129 (46.7903, -11.5923)
    point P130 (46.7903, -11.5923)
    point P131 (47.0653, -11.5671)
    point P132 (47.0653, -11.5671)
    point P133 (47.3537, -11.5355)
    point P134 (47.3537, -11.5355)
    point P135 (47.6553, -11.4971)
    point P136 (47.6553, -11.4971)
    point P137 (47.97, -11.4515)
    point P138 (47.97, -11.4515)
    point P139 (48.2975, -11.3982)
    point P140 (48.2975, -11.3982)
    point P141 (48.6378, -11.3366)
    point P142 (48.6378, -11.3366)
    point P143 (48.7881, -11.3067)
    point P144 (48.7881, -11.3067)
    point P145 (48.8043, -11.3017)
    point P146 (48.8043, -11.3017)
    point P147 (48.8862, -11.2588)
    point P148 (48.8862, -11.2588)
    point P149 (49.0385, -11.0825)
    point P150 (49.0385, -11.0825)
    point P155 (49.1037, -10.5436)
    point P156 (49.1037, -10.5436)
    point P157 (49.0303, -10.4075)
    point P158 (49.0303, -10.4075)
    point P159 (48.9973, -10.3727)
    point P160 (48.9973, -10.3727)
    point P161 (48.9773, -10.3576)
    point P162 (48.9773, -10.3576)
    point P163 (48.7297, -10.1793)
    point P164 (48.7297, -10.1793)
    point P165 (48.4513, -9.9862)
    point P166 (48.4513, -9.9862)
    point P167 (48.1812, -9.8057)
    point P168 (48.1812, -9.8057)
    point P169 (47.9196, -9.6375)
    point P170 (47.9196, -9.6375)
    point P171 (47.667, -9.4811)
    point P172 (47.667, -9.4811)
    point P173 (47.4236, -9.3364)
    point P174 (47.4236, -9.3364)
    point P175 (47.1899, -9.2028)
    point P176 (47.1899, -9.2028)
    point P177 (46.966, -9.0799)
    point P178 (46.966, -9.0799)
    point P179 (46.7523, -8.9675)
    point P180 (46.7523, -8.9675)
    point P181 (46.5492, -8.8651)
    point P182 (46.5492, -8.8651)
    point P187 (46.666, -7.6016)
    point P188 (46.666, -7.6016)
    point P189 (46.8853, -7.5776)
    point P190 (46.8853, -7.5776)
    point P191 (47.1179, -7.548)
    point P192 (47.1179, -7.548)
    point P193 (47.3637, -7.5124)
    point P194 (47.3637, -7.5124)
    point P195 (47.6226, -7.4702)
    point P196 (47.6226, -7.4702)
    point P197 (47.8944, -7.421)
    point P198 (47.8944, -7.421)
    point P199 (48.1789, -7.3644)
    point P200 (48.1789, -7.3644)
    point P201 (48.476, -7.2999)
    point P202 (48.476, -7.2999)
    point P203 (48.7855, -7.2271)
    point P204 (48.7855, -7.2271)
    point P205 (49.1071, -7.1454)
    point P206 (49.1071, -7.1454)
    point P207 (49.4407, -7.0544)
    point P208 (49.4407, -7.0544)
    point P209 (49.5879, -7.0115)
    point P210 (49.5879, -7.0115)
    point P211 (49.6036, -7.0052)
    point P212 (49.6036, -7.0052)
    point P213 (49.6814, -6.9552)
    point P214 (49.6814, -6.9552)
    point P215 (49.8178, -6.7664)
    point P216 (49.8178, -6.7664)
    point P221 (49.8358, -6.2238)
    point P222 (49.8358, -6.2238)
    point P223 (49.7508, -6.0946)
    point P224 (49.7508, -6.0946)
    point P225 (49.7149, -6.0629)
    point P226 (49.7149, -6.0629)
    point P227 (49.6937, -6.0495)
    point P228 (49.6937, -6.0495)
    point P229 (49.4314, -5.8935)
    point P230 (49.4314, -5.8935)
    point P231 (49.1373, -5.7254)
    point P232 (49.1373, -5.7254)
    point P233 (48.8524, -5.5691)
    point P234 (48.8524, -5.5691)
    point P235 (48.5772, -5.4243)
    point P236 (48.5772, -5.4243)
    point P237 (48.3119, -5.2906)
    point P238 (48.3119, -5.2906)
    point P239 (48.0569, -5.1676)
    point P240 (48.0569, -5.1676)
    point P241 (47.8124, -5.0549)
    point P242 (47.8124, -5.0549)
    point P243 (47.5787, -4.952)
    point P244 (47.5787, -4.952)
    point P245 (47.356, -4.8587)
    point P246 (47.356, -4.8587)
    point P247 (47.1447, -4.7744)
    point P248 (47.1447, -4.7744)
    point P253 (47.151, -3.5055)
    point P254 (47.151, -3.5055)
    point P255 (47.3673, -3.4624)
    point P256 (47.3673, -3.4624)
    point P257 (47.5964, -3.4127)
    point P258 (47.5964, -3.4127)
    point P259 (47.8382, -3.3558)
    point P260 (47.8382, -3.3558)
    point P261 (48.0924, -3.2912)
    point P262 (48.0924, -3.2912)
    point P263 (48.3589, -3.2185)
    point P264 (48.3589, -3.2185)
    point P265 (48.6374, -3.1374)
    point P266 (48.6374, -3.1374)
    point P267 (48.9278, -3.0472)
    point P268 (48.9278, -3.0472)
    point P269 (49.2297, -2.9476)
    point P270 (49.2297, -2.9476)
    point P271 (49.543, -2.8382)
    point P272 (49.543, -2.8382)
    point P273 (49.8674, -2.7185)
    point P274 (49.8674, -2.7185)
    point P275 (50.0103, -2.663)
    point P276 (50.0103, -2.663)
    point P277 (50.0254, -2.6553)
    point P278 (50.0254, -2.6553)
    point P279 (50.0986, -2.5988)
    point P280 (50.0986, -2.5988)
    point P281 (50.2179, -2.3987)
    point P282 (50.2179, -2.3987)
    point P287 (50.1886, -1.8566)
    point P288 (50.1886, -1.8566)
    point P289 (50.0926, -1.7353)
    point P290 (50.0926, -1.7353)
    point P291 (50.0541, -1.7068)
    point P292 (50.0541, -1.7068)
    point P293 (50.0318, -1.6954)
    point P294 (50.0318, -1.6954)
    point P295 (49.757, -1.5629)
    point P296 (49.757, -1.5629)
    point P297 (49.4493, -1.421)
    point P298 (49.4493, -1.421)
    point P299 (49.1519, -1.2902)
    point P300 (49.1519, -1.2902)
    point P301 (48.8651, -1.1699)
    point P302 (48.8651, -1.1699)
    point P303 (48.5892, -1.0598)
    point P304 (48.5892, -1.0598)
    point P305 (48.3244, -0.9595)
    point P306 (48.3244, -0.9595)
    point P307 (48.071, -0.8685)
    point P308 (48.071, -0.8685)
    point P309 (47.8292, -0.7864)
    point P310 (47.8292, -0.7864)
    point P311 (47.5993, -0.7128)
    point P312 (47.5993, -0.7128)
    point P313 (47.3814, -0.6473)
    point P314 (47.3814, -0.6473)
    point P319 (-47.2771, -0.6174)
    point P320 (-47.2771, -0.6174)
    point P321 (-47.4888, -0.6791)
    point P322 (-47.4888, -0.6791)
    point P323 (-47.7127, -0.7486)
    point P324 (-47.7127, -0.7486)
    point P325 (-47.9486, -0.8264)
    point P326 (-47.9486, -0.8264)
    point P327 (-48.1963, -0.9129)
    point P328 (-48.1963, -0.9129)
    point P329 (-48.4554, -1.0085)
    point P330 (-48.4554, -1.0085)
    point P331 (-48.7258, -1.1136)
    point P332 (-48.7258, -1.1136)
    point P333 (-49.0072, -1.2287)
    point P334 (-49.0072, -1.2287)
    point P335 (-49.2993, -1.3542)
    point P336 (-49.2993, -1.3542)
    point P337 (-49.6019, -1.4905)
    point P338 (-49.6019, -1.4905)
    point P339 (-49.9146, -1.638)
    point P340 (-49.9146, -1.638)
    point P341 (-50.0521, -1.7058)
    point P342 (-50.0521, -1.7058)
    point P343 (-50.0665, -1.7148)
    point P344 (-50.0665, -1.7148)
    point P345 (-50.1344, -1.7775)
    point P346 (-50.1344, -1.7775)
    point P347 (-50.2359, -1.9872)
    point P348 (-50.2359, -1.9872)
    point P353 (-50.1595, -2.5247)
    point P354 (-50.1595, -2.5247)
    point P355 (-50.0532, -2.6371)
    point P356 (-50.0532, -2.6371)
    point P357 (-50.0124, -2.6622)
    point P358 (-50.0124, -2.6622)
    point P359 (-49.9892, -2.6716)
    point P360 (-49.9892, -2.6716)
    point P361 (-49.7039, -2.7797)
    point P362 (-49.7039, -2.7797)
    point P363 (-49.385, -2.8942)
    point P364 (-49.385, -2.8942)
    point P365 (-49.0773, -2.9986)
    point P366 (-49.0773, -2.9986)
    point P367 (-48.7811, -3.0934)
    point P368 (-48.7811, -3.0934)
    point P369 (-48.4967, -3.179)
    point P370 (-48.4967, -3.179)
    point P371 (-48.2241, -3.2559)
    point P372 (-48.2241, -3.2559)
    point P373 (-47.9638, -3.3245)
    point P374 (-47.9638, -3.3245)
    point P375 (-47.7157, -3.3851)
    point P376 (-47.7157, -3.3851)
    point P377 (-47.4803, -3.4384)
    point P378 (-47.4803, -3.4384)
    point P379 (-47.2575, -3.4848)
    point P380 (-47.2575, -3.4848)
    point P385 (-47.0434, -4.7355)
    point P386 (-47.0434, -4.7355)
    point P387 (-47.2489, -4.8154)
    point P388 (-47.2489, -4.8154)
    point P389 (-47.4659, -4.9042)
    point P390 (-47.4659, -4.9042)
    point P391 (-47.6941, -5.0022)
    point P392 (-47.6941, -5.0022)
    point P393 (-47.9333, -5.11)
    point P394 (-47.9333, -5.11)
    point P395 (-48.1831, -5.2278)
    point P396 (-48.1831, -5.2278)
    point P397 (-48.4433, -5.3561)
    point P398 (-48.4433, -5.3561)
    point P399 (-48.7136, -5.4953)
    point P400 (-48.7136, -5.4953)
    point P401 (-48.9937, -5.6458)
    point P402 (-48.9937, -5.6458)
    point P403 (-49.2832, -5.808)
    point P404 (-49.2832, -5.808)
    point P405 (-49.5819, -5.9822)
    point P406 (-49.5819, -5.9822)
    point P407 (-49.713, -6.0617)
    point P408 (-49.713, -6.0617)
    point P409 (-49.7265, -6.0719)
    point P410 (-49.7265, -6.0719)
    point P411 (-49.7887, -6.1403)
    point P412 (-49.7887, -6.1403)
    point P413 (-49.8715, -6.358)
    point P414 (-49.8715, -6.358)
    point P419 (-49.7485, -6.8867)
    point P420 (-49.7485, -6.8867)
    point P421 (-49.6329, -6.9895)
    point P422 (-49.6329, -6.9895)
    point P423 (-49.59, -7.0109)
    point P424 (-49.59, -7.0109)
    point P425 (-49.5661, -7.0183)
    point P426 (-49.5661, -7.0183)
    point P427 (-49.2725, -7.1011)
    point P428 (-49.2725, -7.1011)
    point P429 (-48.9448, -7.1873)
    point P430 (-48.9448, -7.1873)
    point P431 (-48.6292, -7.2646)
    point P432 (-48.6292, -7.2646)
    point P433 (-48.3259, -7.3332)
    point P434 (-48.3259, -7.3332)
    point P435 (-48.0351, -7.3937)
    point P436 (-48.0351, -7.3937)
    point P437 (-47.7569, -7.4465)
    point P438 (-47.7569, -7.4465)
    point P439 (-47.4915, -7.4921)
    point P440 (-47.4915, -7.4921)
    point P441 (-47.2391, -7.531)
    point P442 (-47.2391, -7.531)
    point P443 (-46.9999, -7.5635)
    point P444 (-46.9999, -7.5635)
    point P445 (-46.774, -7.5903)
    point P446 (-46.774, -7.5903)
    point P451 (-46.4516, -8.8176)
    point P452 (-46.4516, -8.8176)
    point P453 (-46.6494, -8.9151)
    point P454 (-46.6494, -8.9151)
    point P455 (-46.8579, -9.0225)
    point P456 (-46.8579, -9.0225)
    point P457 (-47.0767, -9.14)
    point P458 (-47.0767, -9.14)
    point P459 (-47.3055, -9.2682)
    point P460 (-47.3055, -9.2682)
    point P461 (-47.5441, -9.4073)
    point P462 (-47.5441, -9.4073)
    point P463 (-47.7922, -9.5578)
    point P464 (-47.7922, -9.5578)
    point P465 (-48.0493, -9.7201)
    point P466 (-48.0493, -9.7201)
    point P467 (-48.3152, -9.8944)
    point P468 (-48.3152, -9.8944)
    point P469 (-48.5895, -10.0812)
    point P470 (-48.5895, -10.0812)
    point P471 (-48.8719, -10.2807)
    point P472 (-48.8719, -10.2807)
    point P473 (-48.9955, -10.3714)
    point P474 (-48.9955, -10.3714)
